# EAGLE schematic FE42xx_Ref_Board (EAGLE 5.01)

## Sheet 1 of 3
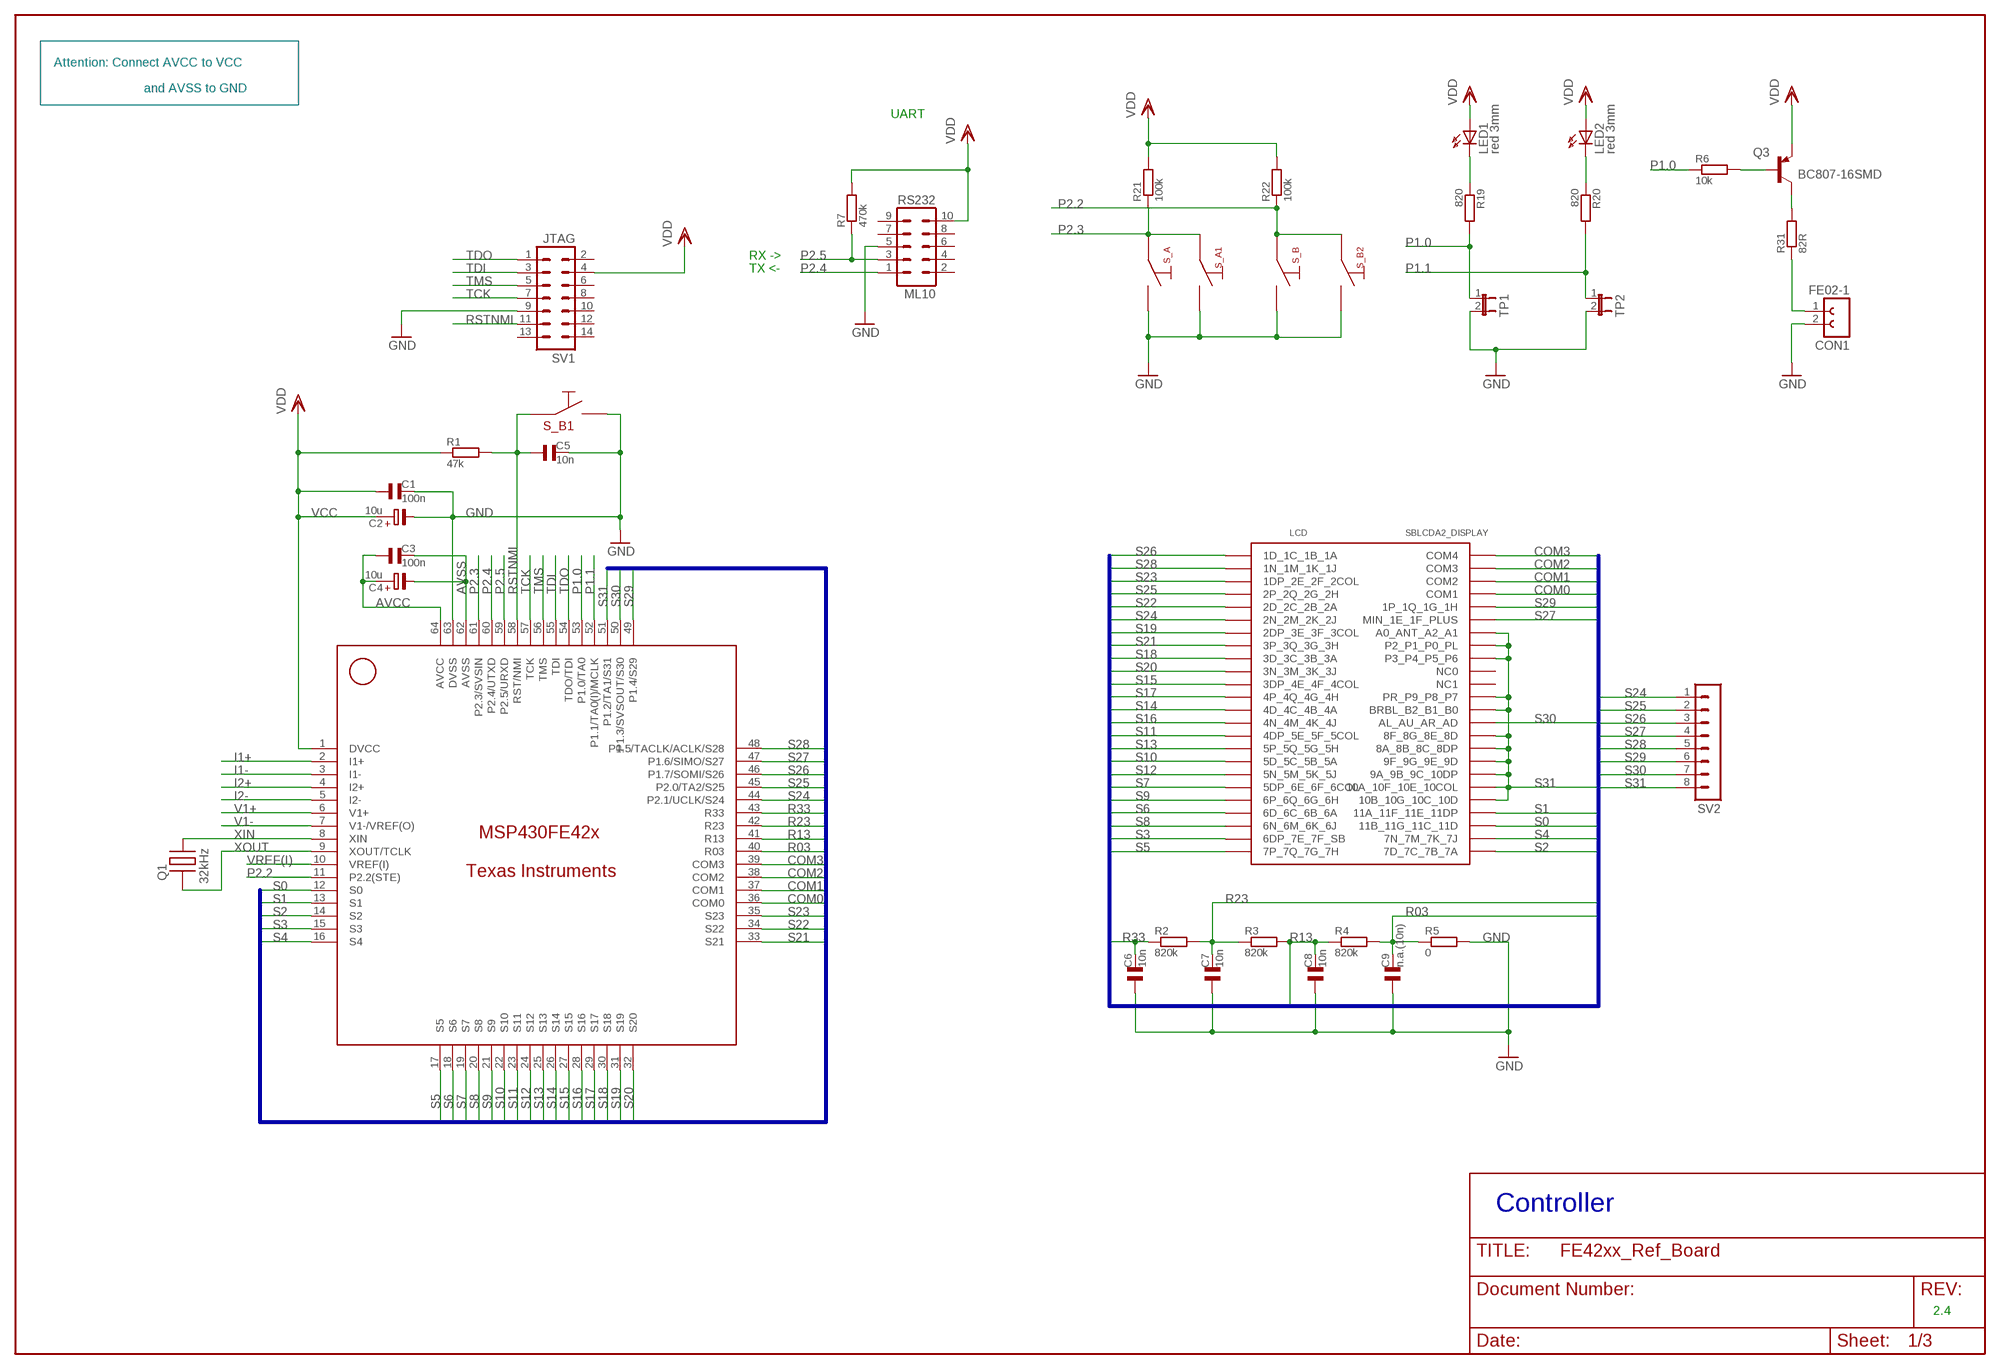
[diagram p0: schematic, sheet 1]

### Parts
C1  100n  CSMD0805  [CSMD0805]
C2  10u  ELKO_1210  [1210ELKO]
C3  100n  CSMD0805  [CSMD0805]
C4  10u  ELKO_1210  [1210ELKO]
C5  10n  CSMD0805  [CSMD0805]
C6  10n  CSMD0805  [CSMD0805]
C7  10n  CSMD0805  [CSMD0805]
C8  10n  CSMD0805  [CSMD0805]
C9  n.a.(10n)  CSMD0805  [CSMD0805]
CON1  FE02-1  [FE02-1]
LCD  SBLCDA2_DISPLAY  [SBLCDA2]
LED1  red 3mm  LED3MM  [LED3MM]
LED2  red 3mm  LED3MM  [LED3MM]
MSP1  FE427_CHIP  [QFP64PM]
Q1  32kHz  QUARZ32K  [QUARZ32K]
Q3  BC807-16SMD  [SOT23-BEC]
R1  47k  R_0805  [0805]
R2  820k  R_0805  [0805]
R3  820k  R_0805  [0805]
R4  820k  R_0805  [0805]
R5  0  R_0805  [0805]
R6  10k  R_0805  [0805]
R7  470k  R_0805  [0805]
R19  820  R_0805  [0805]
R20  820  R_0805  [0805]
R21  100k  R_0805  [0805]
R22  100k  R_0805  [0805]
R31  82R  R_0805  [0805]
RS232  ML10  [ML10]
S_A  TASTER  [TASTER]
S_A1  TASTER  [TASTER]
S_B  TASTER  [TASTER]
S_B1  TASTER  [TASTER]
S_B2  TASTER  [TASTER]
SV1  JTAG  ML14  [ML14]
SV2  MA08-1  [MA08-1]
TP1  JP1E  [JP1]
TP2  JP1E  [JP1]

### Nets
AVCC: C3.1 C4.+ MSP1.64(AVCC) ; also sheet 3
AVSS: C3.2 C4.- MSP1.62(AVSS) ; also sheet 2,3
COM0: LCD.P$45(COM1) MSP1.36(COM0)
COM1: LCD.P$46(COM2) MSP1.37(COM1)
COM2: LCD.P$47(COM3) MSP1.38(COM2)
COM3: LCD.P$48(COM4) MSP1.39(COM3)
GND: C1.2 C2.- C5.2 C6.1 C7.1 C8.1 C9.1 CON1.2 MSP1.63(DVSS) R5.2 RS232.5 S_A1.TASTER1 S_A.TASTER1 S_B1.TASTER1 S_B2.TASTER1 S_B.TASTER1 SV1.9 TP1.2 TP2.2 ; also sheet 3
I1+: MSP1.2(I1+) ; also sheet 2
I1-: MSP1.3(I1-) ; also sheet 2
I2+: MSP1.4(I2+) ; also sheet 2
I2-: MSP1.5(I2-) ; also sheet 2
N$1: Q3.B R6.2
N$17: LED1.K(C) R19.1
N$18: LED2.K(C) R20.1
N$453: CON1.1 R31.1
N$454: Q3.C R31.2
P1.0: MSP1.53(P1.0/TA0) R6.1 R19.2 TP1.1
P1.1: MSP1.52(P1.1/TA0(I)/MCLK) R20.2 TP2.1
P2.2: MSP1.11(P2.2(STE)) R22.1 S_B2.P$1 S_B.P$1
P2.3: MSP1.61(P2.3/SVSIN) R21.1 S_A1.P$1 S_A.P$1
P2.4: MSP1.60(P2.4/UTXD) RS232.1
P2.5: MSP1.59(P2.5/URXD) R7.1 RS232.3
R03: C9.2 MSP1.40(R03) R4.2 R5.1
R13: C8.2 MSP1.41(R13) R3.2 R4.1
R23: C7.2 MSP1.42(R23) R2.2 R3.1
R33: C6.2 MSP1.43(R33) R2.1
RSTNMI: C5.1 MSP1.58(RST/NMI) R1.2 S_B1.P$1 SV1.11
S0: LCD.P$27(11B_11G_11C_11D) MSP1.12(S0)
S1: LCD.P$28(11A_11F_11E_11DP) MSP1.13(S1)
S2: LCD.P$25(7D_7C_7B_7A) MSP1.14(S2)
S3: LCD.P$23(6DP_7E_7F_SB) MSP1.15(S3)
S4: LCD.P$26(7N_7M_7K_7J) MSP1.16(S4)
S5: LCD.P$24(7P_7Q_7G_7H) MSP1.17(S5)
S6: LCD.P$21(6D_6C_6B_6A) MSP1.18(S6)
S7: LCD.P$19(5DP_6E_6F_6COL) MSP1.19(S7)
S8: LCD.P$22(6N_6M_6K_6J) MSP1.20(S8)
S9: LCD.P$20(6P_6Q_6G_6H) MSP1.21(S9)
S10: LCD.P$17(5D_5C_5B_5A) MSP1.22(S10)
S11: LCD.P$15(4DP_5E_5F_5COL) MSP1.23(S11)
S12: LCD.P$18(5N_5M_5K_5J) MSP1.24(S12)
S13: LCD.P$16(5P_5Q_5G_5H) MSP1.25(S13)
S14: LCD.P$13(4D_4C_4B_4A) MSP1.26(S14)
S15: LCD.P$11(3DP_4E_4F_4COL) MSP1.27(S15)
S16: LCD.P$14(4N_4M_4K_4J) MSP1.28(S16)
S17: LCD.P$12(4P_4Q_4G_4H) MSP1.29(S17)
S18: LCD.P$9(3D_3C_3B_3A) MSP1.30(S18)
S19: LCD.P$7(2DP_3E_3F_3COL) MSP1.31(S19)
S20: LCD.P$10(3N_3M_3K_3J) MSP1.32(S20)
S21: LCD.P$8(3P_3Q_3G_3H) MSP1.33(S21)
S22: LCD.P$5(2D_2C_2B_2A) MSP1.34(S22)
S23: LCD.P$3(1DP_2E_2F_2COL) MSP1.35(S23)
S24: LCD.P$6(2N_2M_2K_2J) MSP1.44(P2.1/UCLK/S24) SV2.1
S25: LCD.P$4(2P_2Q_2G_2H) MSP1.45(P2.0/TA2/S25) SV2.2
S26: LCD.P$1(1D_1C_1B_1A) MSP1.46(P1.7/SOMI/S26) SV2.3
S27: LCD.P$43(MIN_1E_1F_PLUS) MSP1.47(P1.6/SIMO/S27) SV2.4
S28: LCD.P$2(1N_1M_1K_1J) MSP1.48(P1.5/TACLK/ACLK/S28) SV2.5
S29: LCD.P$44(1P_1Q_1G_1H) MSP1.49(P1.4/S29) SV2.6
S30: LCD.P$35(AL_AU_AR_AD) MSP1.50(P1.3/SVSOUT/S30) SV2.7
S31: LCD.P$29(10B_10G_10C_10D) LCD.P$30(10A_10F_10E_10COL) LCD.P$31(9A_9B_9C_10DP) LCD.P$32(9F_9G_9E_9D) LCD.P$33(8A_8B_8C_8DP) LCD.P$34(8F_8G_8E_8D) LCD.P$36(BRBL_B2_B1_B0) LCD.P$37(PR_P9_P8_P7) LCD.P$40(P3_P4_P5_P6) LCD.P$41(P2_P1_P0_PL) LCD.P$42(A0_ANT_A2_A1) MSP1.51(P1.2/TA1/S31) SV2.8
TCK: MSP1.57(TCK) SV1.7
TDI: MSP1.55(TDI) SV1.3
TDO: MSP1.54(TDO/TDI) SV1.1
TMS: MSP1.56(TMS) SV1.5
V1+: MSP1.6(V1+) ; also sheet 2
V1-: MSP1.7(V1-/VREF(O)) ; also sheet 2
VCC: C1.1 C2.+ LED1.A LED2.A MSP1.1(DVCC) Q3.E R1.1 R7.2 R21.2 R22.2 RS232.10 SV1.4 ; supply symbol labelled VDD ; also sheet 3
VREF(I): MSP1.10(VREF(I)) ; also sheet 2
XIN: MSP1.8(XIN) Q1.2
XOUT: MSP1.9(XOUT/TCLK) Q1.1
Unconnected: LCD.P$38(NC1) LCD.P$39(NC0) RS232.2 RS232.4 RS232.6 RS232.7 RS232.8 RS232.9 SV1.2 SV1.6 SV1.8 SV1.10 SV1.12 SV1.13 SV1.14

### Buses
S[0..31],COM[0..3],R03,R13,R23,R33

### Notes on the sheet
- Attention: Connect AVCC to VCC
- and AVSS to GND
- UART
- RX ->
- TX <-
- Controller
- 2.4

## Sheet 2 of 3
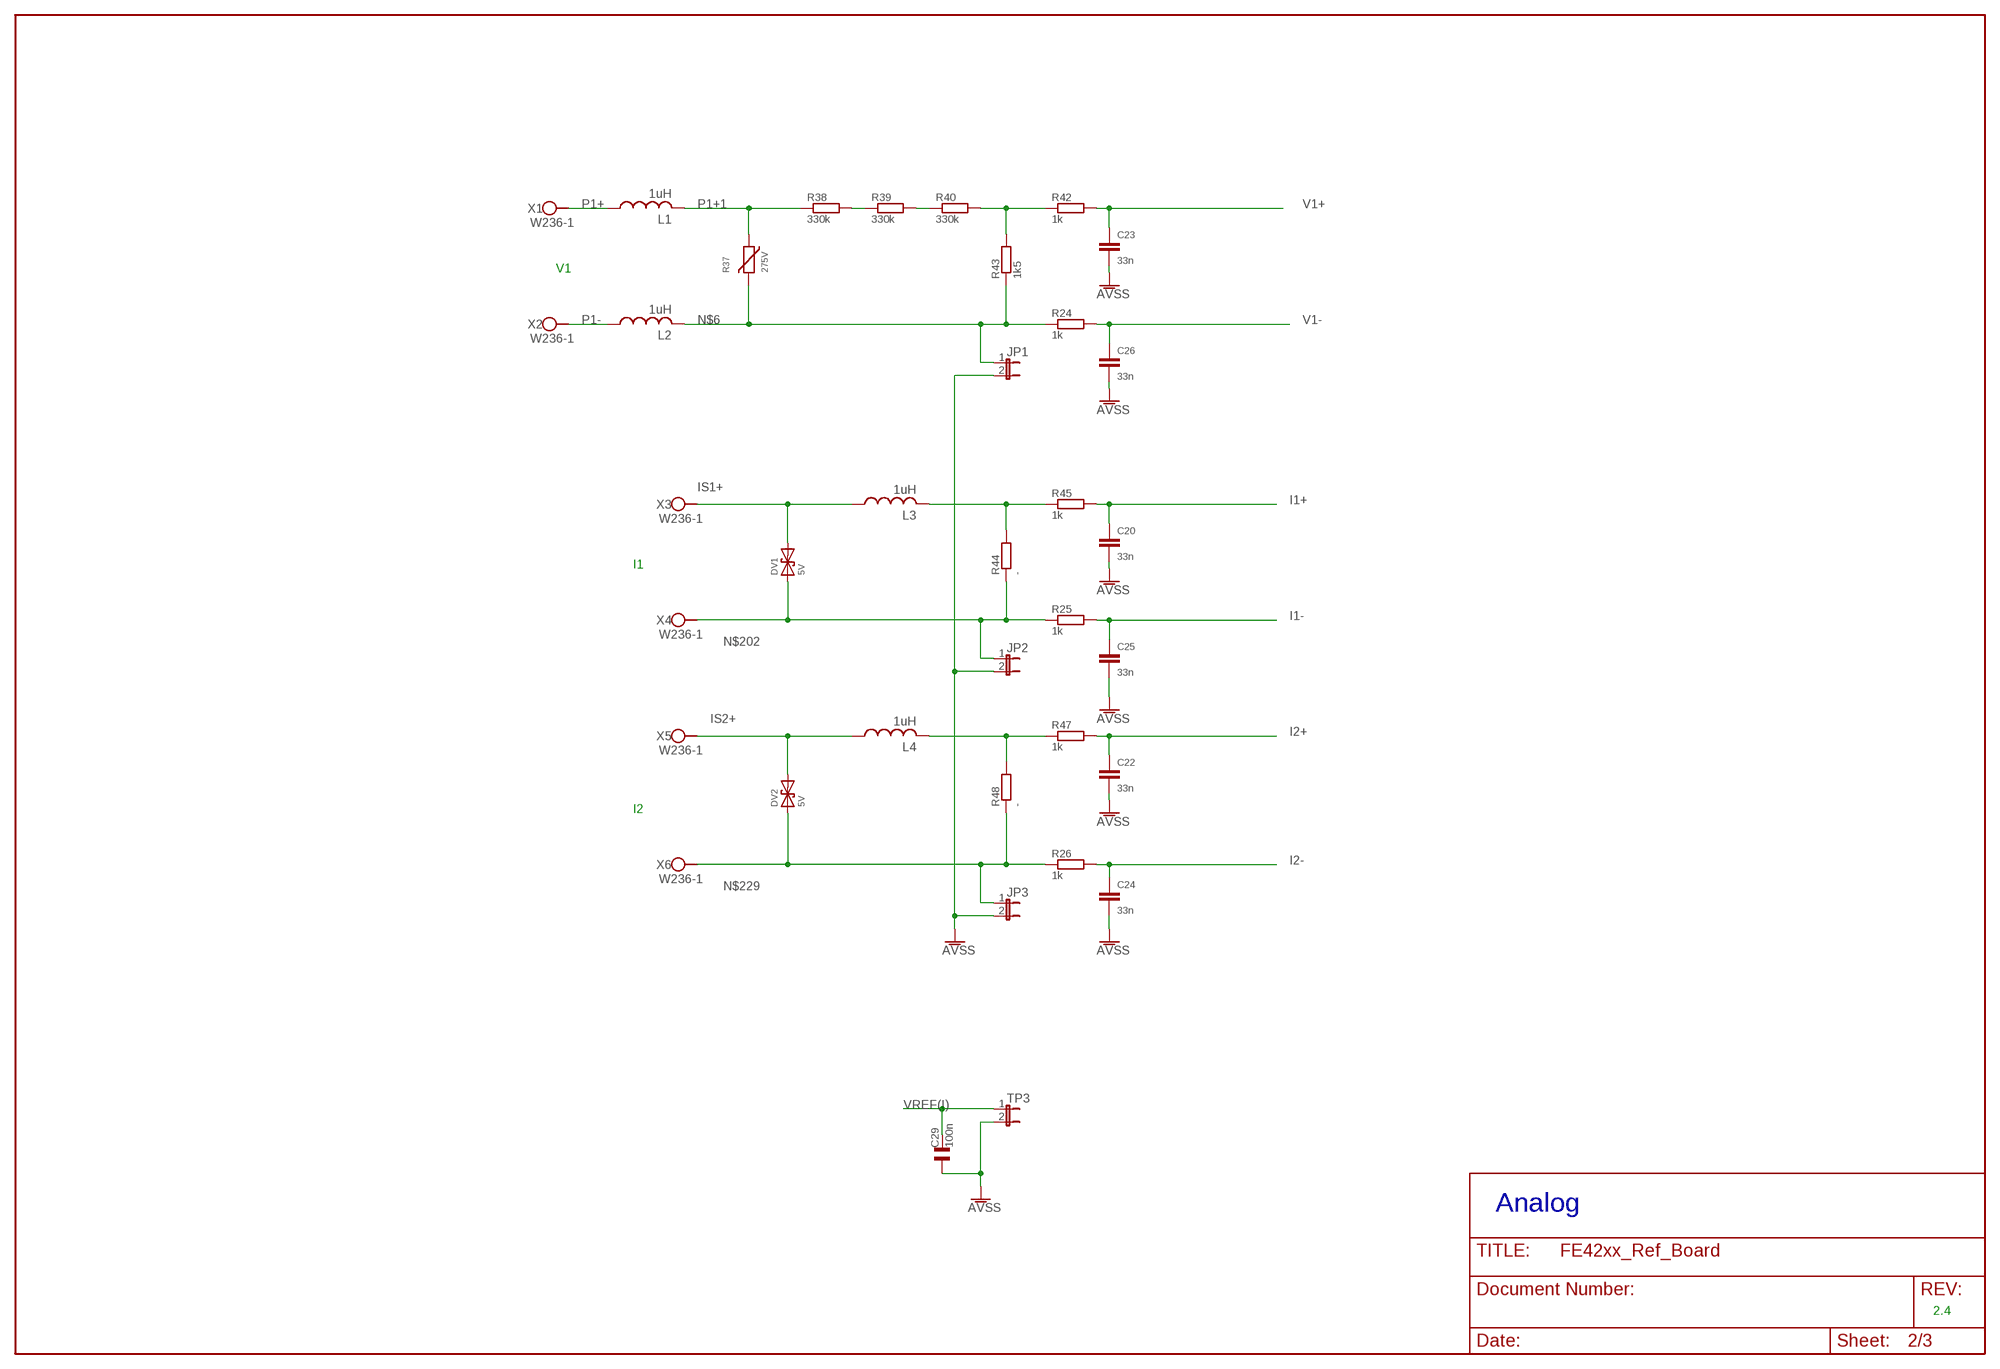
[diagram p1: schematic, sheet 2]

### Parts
C20  33n  C-EUC4532  [C4532]
C22  33n  C-EUC4532  [C4532]
C23  33n  C-EUC4532  [C4532]
C24  33n  C-EUC4532  [C4532]
C25  33n  C-EUC4532  [C4532]
C26  33n  C-EUC4532  [C4532]
C29  100n  C  [0805]
DV1  5V  D_SUPPRESS  [RS-2,5]
DV2  5V  D_SUPPRESS  [RS-2,5]
JP1  JP1E  [JP1]
JP2  JP1E  [JP1]
JP3  JP1E  [JP1]
L1  1uH  L-US08050805  [0805]
L2  1uH  L-US08050805  [0805]
L3  1uH  L-US08050805  [0805]
L4  1uH  L-US08050805  [0805]
R24  1k  R_0805  [0805]
R25  1k  R_0805  [0805]
R26  1k  R_0805  [0805]
R37  275V  VARISTOR-2,5  [R-5]
R38  330k  R_0805  [0805]
R39  330k  R_0805  [0805]
R40  330k  R_0805  [0805]
R42  1k  R_0805  [0805]
R43  1k5  R_0805  [0805]
R44  -  R_0805  [0805]
R45  1k  R_0805  [0805]
R47  1k  R_0805  [0805]
R48  -  R_0805  [0805]
TP3  JP1E  [JP1]
X1  W236-1  [W236-1]
X2  W236-1  [W236-1]
X3  W236-1  [W236-1]
X4  W236-1  [W236-1]
X5  W236-1  [W236-1]
X6  W236-1  [W236-1]

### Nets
AVSS: C20.2 C22.2 C23.2 C24.2 C25.2 C26.2 C29.1 JP1.2 JP2.2 JP3.2 TP3.2 ; also sheet 1,3
I1+: C20.1 R45.2 ; also sheet 1
I1-: C25.1 R25.2 ; also sheet 1
I2+: C22.1 R47.2 ; also sheet 1
I2-: C24.1 R26.2 ; also sheet 1
IS1+: DV1.2 L3.1 X3.1(KL1)
IS2+: DV2.2 L4.1 X5.1(KL1)
N$3: L4.2 R47.1 R48.2
N$6: JP1.1 L2.2 R24.1 R37.2 R43.1
N$8: L3.2 R44.2 R45.1
N$33: R38.2 R39.1
N$45: R39.2 R40.1
N$46: R40.2 R42.1 R43.2
N$202: DV1.1 JP2.1 R25.1 R44.1 X4.1(KL1)
N$229: DV2.1 JP3.1 R26.1 R48.1 X6.1(KL1)
P1+: L1.1 X1.1(KL1) ; also sheet 3
P1+1: L1.2 R37.1 R38.1
P1-: L2.1 X2.1(KL1) ; also sheet 3
V1+: C23.1 R42.2 ; also sheet 1
V1-: C26.1 R24.2 ; also sheet 1
VREF(I): C29.2 TP3.1 ; also sheet 1
Unconnected: X1.2(KL2) X2.2(KL2) X3.2(KL2) X4.2(KL2) X5.2(KL2) X6.2(KL2)

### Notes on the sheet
- V1
- I1
- I2
- Analog
- 2.4

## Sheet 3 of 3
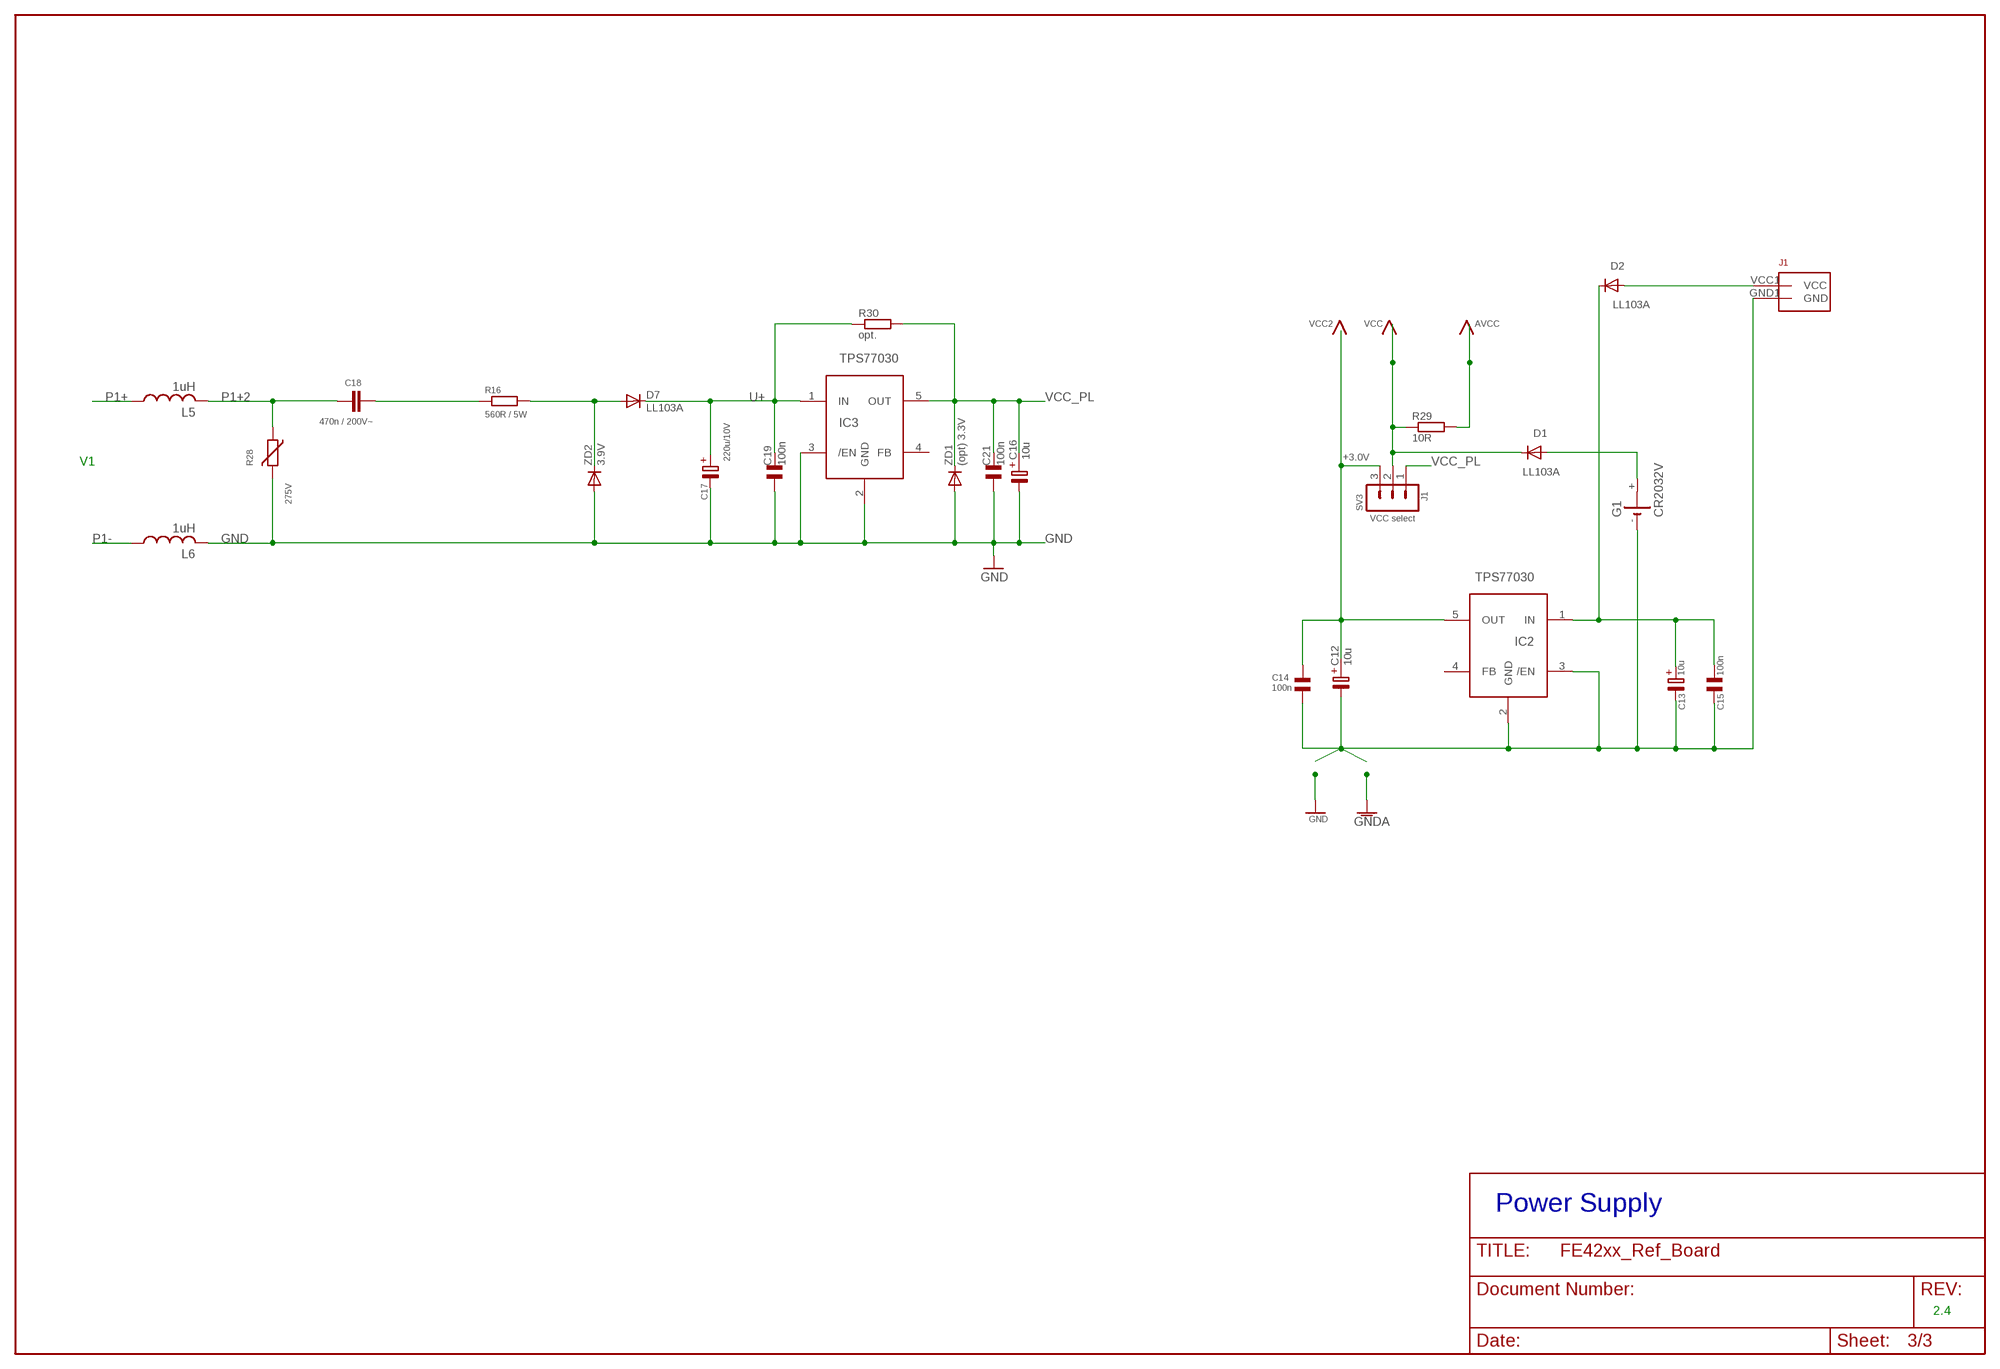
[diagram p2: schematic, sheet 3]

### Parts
C12  10u  ELKO_1210  [1210ELKO]
C13  10u  ELKO  [7243]
C14  100n  C  [0805]
C15  100n  C  [0805]
C16  10u  ELKO_1210  [1210ELKO]
C17  220u/10V  ELKO  [7243]
C18  470n / 200V~  C-EU225-062X268  [C225-062X268]
C19  100n  CSMD0805  [CSMD0805]
C21  100n  CSMD0805  [CSMD0805]
D1  LL103A  D  [SOD-80]
D2  LL103A  D  [SOD-80]
D7  LL103A  D  [SOD-80]
G1  CR2032V  [CR2032V]
IC2  TPS77030  TPS77001  [SOT23/5]
IC3  TPS77030  TPS77001  [SOT23/5]
J1  SUP_CON  [SUP_CON]
L5  1uH  L-US08050805  [0805]
L6  1uH  L-US08050805  [0805]
R16  560R / 5W  R-EU_0817/7V  [P0817V]
R28  275V  VARISTOR-2,5  [R-5]
R29  10R  R_0805  [0805]
R30  opt.  R_0805  [0805]
SV3  VCC select  MA03-1@2  [MA03-1@2]
ZD1  (opt) 3.3V  D  [SOD-80]
ZD2  3.9V  D  [SOD-80]

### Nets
AVCC: R29.2 ; also sheet 1
GND: C12.- C13.1 C14.1 C15.1 C16.- C17.1 C19.1 C21.1 G1.- IC2.2(GND) IC2.3(/EN) IC3.2(GND) IC3.3(/EN) J1.GND2(GND1) L6.2 R28.2 ZD1.1(A) ZD2.1(A) ; also sheet 1
N$5: D7.1(A) R16.2 ZD2.2(K)
N$10: C18.2 R16.1
N$35: C13.2 C15.2 D2.2(K) IC2.1(IN)
N$48: D1.1(A) G1.+
P1+: L5.1 ; also sheet 2
P1+2: C18.1 L5.2 R28.1
P1-: L6.1 ; also sheet 2
U+: C17.2 C19.2 D7.2(K) IC3.1(IN) R30.1
VCC: D1.2(K) R29.1 SV3.2 ; also sheet 1
VCC1: D2.1(A) J1.VCC2
VCC2: C12.+ C14.2 IC2.5(OUT) SV3.3
VCC_PL: C16.+ C21.2 IC3.5(OUT) R30.2 SV3.1 ZD1.2(K)
Unconnected: G1.+@1(+) IC2.4(FB) IC3.4(FB) J1.GND1(GND) J1.VCC1(VCC)

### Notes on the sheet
- AVCC
- +3.0V
- V1
- J1
- Power Supply
- 2.4

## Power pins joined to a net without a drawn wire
GND: Q1.GND

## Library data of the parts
C1 C3 C5-C9 C19 C21 = CAP:CSMD0805
C2 C4 C12 C16 = SMD:ELKO_1210
C13 C17 = SMD-CAP:ELKO
C14 C15 C29 = SMD-CAP:C
C18 C20 C22-C26 = rcl:C-EU: CAPACITOR, European symbol
CON1 = con-lsta:FE02-1
D1 D2 D7 ZD1 ZD2 = SMD:D
DV1 DV2 = E-Meter:D_SUPPRESS
G1 = battery:CR2032V: LI BATTERY Varta
IC2 IC3 = flash-evk:TPS77001
J1 = F148:SUP_CON
JP1-JP3 TP1-TP3 = jumper:JP1E: JUMPER
L1-L6 = SMD:L-US0805
LCD = Display-SoftBaugh:SBLCDA2: SBLCDA2 Display by SoftBaugh
LED1 LED2 = LED:LED: LED
MSP1 = FE427:FE427_CHIP: FW427 device as SMD
Q1 = MSP430:QUARZ32K
Q3 = transistor-pnp:BC807*: PNP Transistror
R1-R7 R19-R22 R24-R26 R29-R31 R38-R40 R42-R45 R47 R48 = SMD:R_0805
R16 = rcl:R-EU_: RESISTOR, European symbol
R28 R37 = varistor:VARISTOR: VARISTOR
RS232 = con-ml:ML10
S_A S_A1 S_B S_B1 S_B2 = F148:TASTER
SV1 = con-ml:ML14: HARTING
SV2 = CON-LSTB:MA08-1: PIN HEADER
SV3 = CON-LSTB:MA03-1@2
X1-X6 = con-wago-508:W236-1: WAGO SREW CLAMP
